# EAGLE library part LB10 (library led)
LED BLOCK 10-LED bar graph, DIL, Siemens
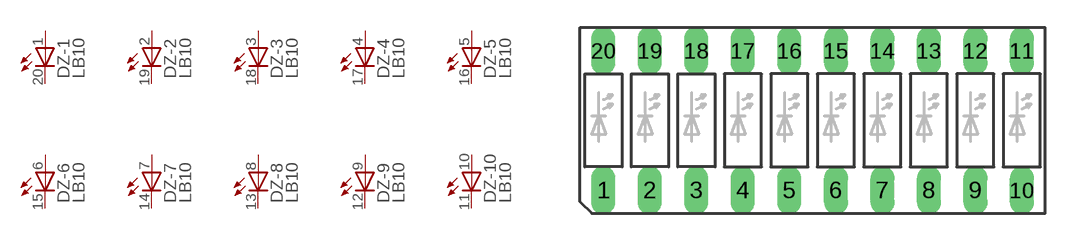
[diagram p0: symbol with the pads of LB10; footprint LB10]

Designator prefix DZ; gates -1=LED-A -2=LED-A -3=LED-A -4=LED-A -5=LED-A -6=LED-A -7=LED-A -8=LED-A -9=LED-A -10=LED-A

## LB10  [LB10]
1  -1:A  pas
2  -2:A  pas
3  -3:A  pas
4  -4:A  pas
5  -5:A  pas
6  -6:A  pas
7  -7:A  pas
8  -8:A  pas
9  -9:A  pas
10  -10:A  pas
11  -10:C  pas
12  -9:C  pas
13  -8:C  pas
14  -7:C  pas
15  -6:C  pas
16  -5:C  pas
17  -4:C  pas
18  -3:C  pas
19  -2:C  pas
20  -1:C  pas

## Footprint LB10 (pad centres in mm)
LED BLOCK 10-LED bar graph, DIL, Siemens
drill 0.813 long: 1 -11.43,-3.81; 2 -8.89,-3.81; 3 -6.35,-3.81; 4 -3.81,-3.81; 5 -1.27,-3.81; 6 1.27,-3.81; 7 3.81,-3.81; 8 6.35,-3.81; 9 8.89,-3.81; 10 11.43,-3.81; 11 11.43,3.81; 12 8.89,3.81; 13 6.35,3.81; 14 3.81,3.81; 15 1.27,3.81; 16 -1.27,3.81; 17 -3.81,3.81; 18 -6.35,3.81; 19 -8.89,3.81; 20 -11.43,3.81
